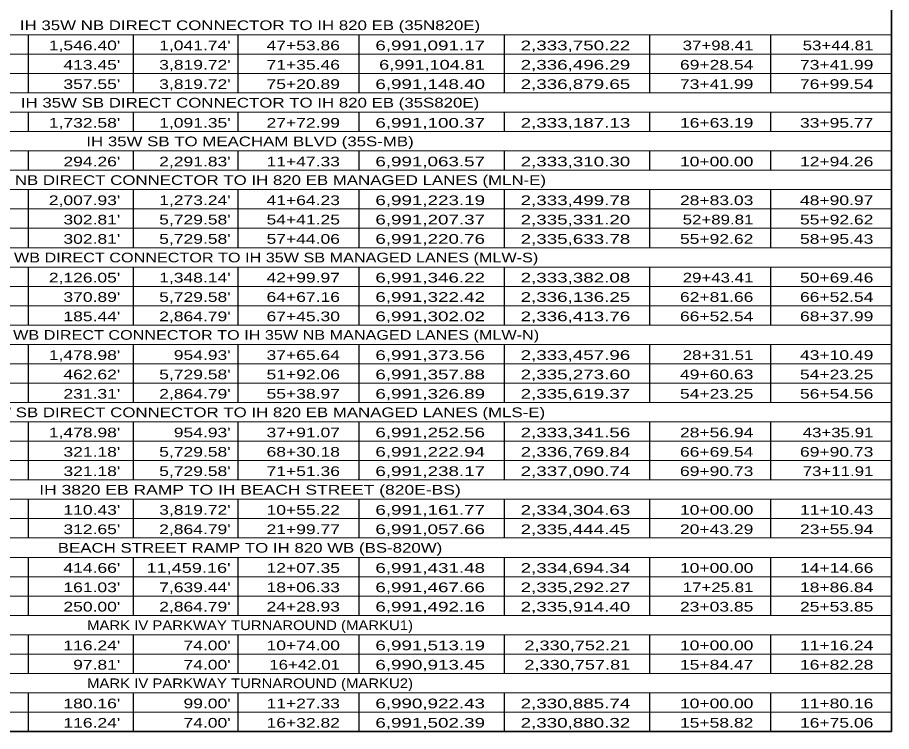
# Model space of a CAD drawing. Extents: x 1953053 to 1967065, y 7363860 to 7371201.
# Drawn here: x 1956574 to 1957657, y 7367608 to 7368493 of the extents above; entities that cross this region are included whole.
import ezdxf
from ezdxf.enums import TextEntityAlignment as Align

# ---------------------------------------------------------------- set-up
doc = ezdxf.new("R2010")
doc.units = 0
doc.header["$LTSCALE"] = 4.8
doc.layers.add('10', color=7, linetype='Continuous')
doc.layers.add('12', color=7, linetype='Continuous', lineweight=25)

msp = doc.modelspace()

# ---------------------------------------------------------------- linework, layer by layer
at = {"layer": '12', "lineweight": 35}
for p, q in [((1957656.717, 7367607.746), (1957656.717, 7370164.879)), ((1955933.385, 7367607.746), (1957656.717, 7367607.746))]:
    msp.add_line(p, q, dxfattribs=at)
at = {"layer": '12', "lineweight": 13}
for p, q in [((1955933.385, 7368471.746), (1957656.717, 7368471.746)), ((1955933.385, 7368447.746), (1957656.717, 7368447.746)), ((1955933.385, 7368423.746), (1957656.717, 7368423.746)), ((1955933.385, 7368399.746), (1957656.717, 7368399.746)), ((1955933.385, 7368375.746), (1957656.717, 7368375.746)), ((1955933.385, 7368351.746), (1957656.717, 7368351.746)), ((1955933.385, 7368327.746), (1957656.717, 7368327.746)), ((1955933.385, 7368303.746), (1957656.717, 7368303.746)), ((1955933.385, 7368279.746), (1957656.717, 7368279.746)), ((1955933.385, 7368255.746), (1957656.717, 7368255.746)), ((1955933.385, 7368231.746), (1957656.717, 7368231.746)), ((1955933.385, 7368207.746), (1957656.717, 7368207.746)), ((1955933.385, 7368183.746), (1957656.717, 7368183.746)), ((1955933.385, 7368159.746), (1957656.717, 7368159.746)), ((1955933.385, 7368135.746), (1957656.717, 7368135.746)), ((1955933.385, 7368111.746), (1957656.717, 7368111.746)), ((1955933.385, 7368087.746), (1957656.717, 7368087.746)), ((1955933.385, 7368063.746), (1957656.717, 7368063.746)), ((1955933.385, 7368039.746), (1957656.717, 7368039.746)), ((1955933.385, 7368015.746), (1957656.717, 7368015.746)), ((1955933.385, 7367991.746), (1957656.717, 7367991.746)), ((1955933.385, 7367967.746), (1957656.717, 7367967.746)), ((1955933.385, 7367943.746), (1957656.717, 7367943.746)), ((1955933.385, 7367919.746), (1957656.717, 7367919.746)), ((1955933.385, 7367895.746), (1957656.717, 7367895.746)), ((1955933.385, 7367871.746), (1957656.717, 7367871.746)), ((1955933.385, 7367847.746), (1957656.717, 7367847.746)), ((1955933.385, 7367823.746), (1957656.717, 7367823.746)), ((1955933.385, 7367799.746), (1957656.717, 7367799.746)), ((1955933.385, 7367775.746), (1957656.717, 7367775.746)), ((1955933.385, 7367751.746), (1957656.717, 7367751.746)), ((1955933.385, 7367727.746), (1957656.717, 7367727.746)), ((1955933.385, 7367703.746), (1957656.717, 7367703.746)), ((1955933.385, 7367679.746), (1957656.717, 7367679.746)), ((1955933.385, 7367655.746), (1957656.717, 7367655.746)), ((1955933.385, 7367631.746), (1957656.717, 7367631.746))]:
    msp.add_line(p, q, dxfattribs=at)
at = {"layer": '12'}
for p, q in [((1956586.717, 7368471.746), (1956586.717, 7368399.746)), ((1956716.717, 7368471.746), (1956716.717, 7368399.746)), ((1956846.717, 7368471.746), (1956846.717, 7368399.746)), ((1956996.717, 7368471.746), (1956996.717, 7368399.746)), ((1957176.717, 7368471.746), (1957176.717, 7368399.746)), ((1957356.717, 7368471.746), (1957356.717, 7368399.746)), ((1957506.717, 7368471.746), (1957506.717, 7368399.746)), ((1956586.717, 7368375.746), (1956586.717, 7368351.746)), ((1956716.717, 7368375.746), (1956716.717, 7368351.746)), ((1956846.717, 7368375.746), (1956846.717, 7368351.746)), ((1956996.717, 7368375.746), (1956996.717, 7368351.746)), ((1957176.717, 7368375.746), (1957176.717, 7368351.746)), ((1957356.717, 7368375.746), (1957356.717, 7368351.746)), ((1957506.717, 7368375.746), (1957506.717, 7368351.746)), ((1956586.717, 7368327.746), (1956586.717, 7368303.746)), ((1956716.717, 7368327.746), (1956716.717, 7368303.746)), ((1956846.717, 7368327.746), (1956846.717, 7368303.746)), ((1956996.717, 7368327.746), (1956996.717, 7368303.746)), ((1957176.717, 7368327.746), (1957176.717, 7368303.746)), ((1957356.717, 7368327.746), (1957356.717, 7368303.746)), ((1957506.717, 7368327.746), (1957506.717, 7368303.746)), ((1956586.717, 7368279.746), (1956586.717, 7368207.746)), ((1956716.717, 7368279.746), (1956716.717, 7368207.746)), ((1956846.717, 7368279.746), (1956846.717, 7368207.746)), ((1956996.717, 7368279.746), (1956996.717, 7368207.746)), ((1957176.717, 7368279.746), (1957176.717, 7368207.746)), ((1957356.717, 7368279.746), (1957356.717, 7368207.746)), ((1957506.717, 7368279.746), (1957506.717, 7368207.746)), ((1956586.717, 7368183.746), (1956586.717, 7368111.746)), ((1956716.717, 7368183.746), (1956716.717, 7368111.746)), ((1956846.717, 7368183.746), (1956846.717, 7368111.746)), ((1956996.717, 7368183.746), (1956996.717, 7368111.746)), ((1957176.717, 7368183.746), (1957176.717, 7368111.746)), ((1957356.717, 7368183.746), (1957356.717, 7368111.746)), ((1957506.717, 7368183.746), (1957506.717, 7368111.746)), ((1956586.717, 7368087.746), (1956586.717, 7368015.746)), ((1956716.717, 7368087.746), (1956716.717, 7368015.746)), ((1956846.717, 7368087.746), (1956846.717, 7368015.746)), ((1956996.717, 7368087.746), (1956996.717, 7368015.746)), ((1957176.717, 7368087.746), (1957176.717, 7368015.746)), ((1957356.717, 7368087.746), (1957356.717, 7368015.746)), ((1957506.717, 7368087.746), (1957506.717, 7368015.746)), ((1956586.717, 7367991.746), (1956586.717, 7367919.746)), ((1956716.717, 7367991.746), (1956716.717, 7367919.746)), ((1956846.717, 7367991.746), (1956846.717, 7367919.746)), ((1956996.717, 7367991.746), (1956996.717, 7367919.746)), ((1957176.717, 7367991.746), (1957176.717, 7367919.746)), ((1957356.717, 7367991.746), (1957356.717, 7367919.746)), ((1957506.717, 7367991.746), (1957506.717, 7367919.746)), ((1956586.717, 7367895.746), (1956586.717, 7367847.746)), ((1956716.717, 7367895.746), (1956716.717, 7367847.746)), ((1956846.717, 7367895.746), (1956846.717, 7367847.746)), ((1956996.717, 7367895.746), (1956996.717, 7367847.746)), ((1957176.717, 7367895.746), (1957176.717, 7367847.746)), ((1957356.717, 7367895.746), (1957356.717, 7367847.746)), ((1957506.717, 7367895.746), (1957506.717, 7367847.746)), ((1956586.717, 7367823.746), (1956586.717, 7367751.746)), ((1956716.717, 7367823.746), (1956716.717, 7367751.746)), ((1956846.717, 7367823.746), (1956846.717, 7367751.746)), ((1956996.717, 7367823.746), (1956996.717, 7367751.746)), ((1957176.717, 7367823.746), (1957176.717, 7367751.746)), ((1957356.717, 7367823.746), (1957356.717, 7367751.746)), ((1957506.717, 7367823.746), (1957506.717, 7367751.746)), ((1956586.717, 7367727.746), (1956586.717, 7367679.746)), ((1956716.717, 7367727.746), (1956716.717, 7367679.746)), ((1956846.717, 7367727.746), (1956846.717, 7367679.746)), ((1956996.717, 7367727.746), (1956996.717, 7367679.746)), ((1957176.717, 7367727.746), (1957176.717, 7367679.746)), ((1957356.717, 7367727.746), (1957356.717, 7367679.746)), ((1957506.717, 7367727.746), (1957506.717, 7367679.746)), ((1956586.717, 7367655.746), (1956586.717, 7367607.746)), ((1956716.717, 7367655.746), (1956716.717, 7367607.746)), ((1956846.717, 7367655.746), (1956846.717, 7367607.746)), ((1956996.717, 7367655.746), (1956996.717, 7367607.746)), ((1957176.717, 7367655.746), (1957176.717, 7367607.746)), ((1957356.717, 7367655.746), (1957356.717, 7367607.746)), ((1957506.717, 7367655.746), (1957506.717, 7367607.746))]:
    msp.add_line(p, q, dxfattribs=at)

# ---------------------------------------------------------------- texts
at = {"layer": '10'}
for s, width, p in [('IH 35W NB DIRECT CONNECTOR TO IH 820 EB (35N820E)', 1.3, (1956861.717, 7368477.54)), ('IH 35W SB DIRECT CONNECTOR TO IH 820 EB (35S820E)', 1.3, (1956861.717, 7368381.54)), ('IH 35W SB TO MEACHAM BLVD (35S-MB)', 1.3, (1956861.718, 7368333.54)), ('IH 35W NB DIRECT CONNECTOR TO IH 820 EB MANAGED LANES (MLN-E)', 1.3, (1956861.718, 7368285.54)), ('IH 820 WB DIRECT CONNECTOR TO IH 35W SB MANAGED LANES (MLW-S)', 1.25, (1956861.718, 7368189.54)), ('IH 820 WB DIRECT CONNECTOR TO IH 35W NB MANAGED LANES (MLW-N)', 1.25, (1956861.718, 7368093.54)), ('IH 35W SB DIRECT CONNECTOR TO IH 820 EB MANAGED LANES (MLS-E)', 1.3, (1956861.718, 7367997.54)), ('IH 3820 EB RAMP TO IH BEACH STREET (820E-BS)', 1.35, (1956861.718, 7367901.54)), ('BEACH STREET RAMP TO IH 820 WB (BS-820W)', 1.3, (1956861.717, 7367829.54)), ('MARK IV PARKWAY TURNAROUND (MARKU1)', 1.15, (1956861.717, 7367733.54)), ('MARK IV PARKWAY TURNAROUND (MARKU2)', 1.15, (1956861.717, 7367661.54))]:
    msp.add_text(s, height=12, dxfattribs=dict(at, width=width)).set_placement(p, align=Align.CENTER)
for s, width, p in [("1,546.40'", 1.35, (1956700.846, 7368452.569)), ("1,041.74'", 1.35, (1956837.615, 7368452.569)), ('47+53.86', 1.35, (1956973.159, 7368452.569)), ('6,991,091.17', 1.45, (1957152.924, 7368452.569)), ('2,333,750.22', 1.45, (1957332.924, 7368452.569)), ('37+98.41', 1.3, (1957485.502, 7368452.569)), ('53+44.81', 1.3, (1957634.234, 7368452.569)), ("413.45'", 1.35, (1956700.846, 7368428.569)), ("3,819.72'", 1.35, (1956837.615, 7368428.569)), ('71+35.46', 1.35, (1956973.159, 7368428.569)), ('6,991,104.81', 1.4, (1957152.924, 7368428.569)), ('2,336,496.29', 1.45, (1957332.924, 7368428.569)), ('69+28.54', 1.35, (1957485.502, 7368428.569)), ('73+41.99', 1.35, (1957634.234, 7368428.569)), ("357.55'", 1.35, (1956700.846, 7368404.569)), ("3,819.72'", 1.35, (1956837.615, 7368404.569)), ('75+20.89', 1.35, (1956973.159, 7368404.569)), ('6,991,148.40', 1.45, (1957152.924, 7368404.569)), ('2,336,879.65', 1.45, (1957332.924, 7368404.569)), ('73+41.99', 1.35, (1957485.502, 7368404.569)), ('76+99.54', 1.35, (1957634.234, 7368404.569)), ("1,732.58'", 1.35, (1956700.846, 7368356.569)), ("1,091.35'", 1.35, (1956837.615, 7368356.569)), ('27+72.99', 1.35, (1956973.159, 7368356.569)), ('6,991,100.37', 1.45, (1957152.924, 7368356.569)), ('2,333,187.13', 1.45, (1957332.924, 7368356.569)), ('16+63.19', 1.35, (1957485.502, 7368356.569)), ('33+95.77', 1.35, (1957634.234, 7368356.569)), ("294.26'", 1.35, (1956700.846, 7368308.569)), ("2,291.83'", 1.35, (1956837.615, 7368308.569)), ('11+47.33', 1.35, (1956973.159, 7368308.569)), ('6,991,063.57', 1.45, (1957152.924, 7368308.569)), ('2,333,310.30', 1.45, (1957332.924, 7368308.569)), ('10+00.00', 1.35, (1957485.502, 7368308.569)), ('12+94.26', 1.35, (1957634.234, 7368308.569)), ("2,007.93'", 1.35, (1956700.846, 7368260.569)), ("1,273.24'", 1.35, (1956837.615, 7368260.569)), ('41+64.23', 1.35, (1956973.159, 7368260.569)), ('6,991,223.19', 1.45, (1957152.924, 7368260.569)), ('2,333,499.78', 1.45, (1957332.924, 7368260.569)), ('28+83.03', 1.35, (1957485.502, 7368260.569)), ('48+90.97', 1.35, (1957634.234, 7368260.569)), ("302.81'", 1.35, (1956700.846, 7368236.569)), ("5,729.58'", 1.35, (1956837.615, 7368236.569)), ('54+41.25', 1.35, (1956973.159, 7368236.569)), ('6,991,207.37', 1.45, (1957152.924, 7368236.569)), ('2,335,331.20', 1.45, (1957332.924, 7368236.569)), ('52+89.81', 1.3, (1957485.502, 7368236.569)), ('55+92.62', 1.35, (1957634.234, 7368236.569)), ("302.81'", 1.35, (1956700.846, 7368212.569)), ("5,729.58'", 1.35, (1956837.615, 7368212.569)), ('57+44.06', 1.35, (1956973.159, 7368212.569)), ('6,991,220.76', 1.45, (1957152.924, 7368212.569)), ('2,335,633.78', 1.45, (1957332.924, 7368212.569)), ('55+92.62', 1.35, (1957485.502, 7368212.569)), ('58+95.43', 1.35, (1957634.234, 7368212.569)), ("2,126.05'", 1.35, (1956700.846, 7368164.569)), ("1,348.14'", 1.35, (1956837.615, 7368164.569)), ('42+99.97', 1.35, (1956973.159, 7368164.569)), ('6,991,346.22', 1.45, (1957152.924, 7368164.569)), ('2,333,382.08', 1.45, (1957332.924, 7368164.569)), ('29+43.41', 1.3, (1957485.502, 7368164.569)), ('50+69.46', 1.35, (1957634.234, 7368164.569)), ("370.89'", 1.35, (1956700.846, 7368140.569)), ("5,729.58'", 1.35, (1956837.615, 7368140.569)), ('64+67.16', 1.35, (1956973.159, 7368140.569)), ('6,991,322.42', 1.45, (1957152.924, 7368140.569)), ('2,336,136.25', 1.45, (1957332.924, 7368140.569)), ('62+81.66', 1.35, (1957485.502, 7368140.569)), ('66+52.54', 1.35, (1957634.234, 7368140.569)), ("185.44'", 1.35, (1956700.846, 7368116.569)), ("2,864.79'", 1.35, (1956837.615, 7368116.569)), ('67+45.30', 1.35, (1956973.159, 7368116.569)), ('6,991,302.02', 1.45, (1957152.924, 7368116.569)), ('2,336,413.76', 1.45, (1957332.924, 7368116.569)), ('66+52.54', 1.35, (1957485.502, 7368116.569)), ('68+37.99', 1.35, (1957634.234, 7368116.569)), ("1,478.98'", 1.35, (1956700.846, 7368068.569)), ("954.93'", 1.35, (1956837.615, 7368068.569)), ('37+65.64', 1.35, (1956973.159, 7368068.569)), ('6,991,373.56', 1.45, (1957152.924, 7368068.569)), ('2,333,457.96', 1.45, (1957332.924, 7368068.569)), ('28+31.51', 1.3, (1957485.502, 7368068.569)), ('43+10.49', 1.35, (1957634.234, 7368068.569)), ("462.62'", 1.35, (1956700.846, 7368044.569)), ("5,729.58'", 1.35, (1956837.615, 7368044.569)), ('51+92.06', 1.35, (1956973.159, 7368044.569)), ('6,991,357.88', 1.45, (1957152.924, 7368044.569)), ('2,335,273.60', 1.45, (1957332.924, 7368044.569)), ('49+60.63', 1.35, (1957485.502, 7368044.569)), ('54+23.25', 1.35, (1957634.234, 7368044.569)), ("231.31'", 1.35, (1956700.846, 7368020.569)), ("2,864.79'", 1.35, (1956837.615, 7368020.569)), ('55+38.97', 1.35, (1956973.159, 7368020.569)), ('6,991,326.89', 1.45, (1957152.924, 7368020.569)), ('2,335,619.37', 1.45, (1957332.924, 7368020.569)), ('54+23.25', 1.35, (1957485.502, 7368020.569)), ('56+54.56', 1.35, (1957634.234, 7368020.569)), ("1,478.98'", 1.35, (1956700.846, 7367972.569)), ("954.93'", 1.35, (1956837.615, 7367972.569)), ('37+91.07', 1.35, (1956973.159, 7367972.569)), ('6,991,252.56', 1.45, (1957152.924, 7367972.569)), ('2,333,341.56', 1.45, (1957332.924, 7367972.569)), ('28+56.94', 1.35, (1957485.502, 7367972.569)), ('43+35.91', 1.3, (1957634.234, 7367972.569)), ("321.18'", 1.35, (1956700.846, 7367948.569)), ("5,729.58'", 1.35, (1956837.615, 7367948.569)), ('68+30.18', 1.35, (1956973.159, 7367948.569)), ('6,991,222.94', 1.45, (1957152.924, 7367948.569)), ('2,336,769.84', 1.45, (1957332.924, 7367948.569)), ('66+69.54', 1.35, (1957485.502, 7367948.569)), ('69+90.73', 1.35, (1957634.234, 7367948.569)), ("321.18'", 1.35, (1956700.846, 7367924.569)), ("5,729.58'", 1.35, (1956837.615, 7367924.569)), ('71+51.36', 1.35, (1956973.159, 7367924.569)), ('6,991,238.17', 1.45, (1957152.924, 7367924.569)), ('2,337,090.74', 1.45, (1957332.924, 7367924.569)), ('69+90.73', 1.35, (1957485.502, 7367924.569)), ('73+11.91', 1.3, (1957634.234, 7367924.569)), ("110.43'", 1.35, (1956700.846, 7367876.569)), ("3,819.72'", 1.35, (1956837.615, 7367876.569)), ('10+55.22', 1.35, (1956973.159, 7367876.569)), ('6,991,161.77', 1.45, (1957152.924, 7367876.569)), ('2,334,304.63', 1.45, (1957332.924, 7367876.569)), ('10+00.00', 1.35, (1957485.502, 7367876.569)), ('11+10.43', 1.35, (1957634.234, 7367876.569)), ("312.65'", 1.35, (1956700.846, 7367852.569)), ("2,864.79'", 1.35, (1956837.615, 7367852.569)), ('21+99.77', 1.35, (1956973.159, 7367852.569)), ('6,991,057.66', 1.45, (1957152.924, 7367852.569)), ('2,335,444.45', 1.45, (1957332.924, 7367852.569)), ('20+43.29', 1.35, (1957485.502, 7367852.569)), ('23+55.94', 1.35, (1957634.234, 7367852.569)), ("414.66'", 1.35, (1956700.846, 7367804.569)), ("11,459.16'", 1.4, (1956837.615, 7367804.569)), ('12+07.35', 1.35, (1956973.159, 7367804.569)), ('6,991,431.48', 1.45, (1957152.924, 7367804.569)), ('2,334,694.34', 1.45, (1957332.924, 7367804.569)), ('10+00.00', 1.35, (1957485.502, 7367804.569)), ('14+14.66', 1.35, (1957634.234, 7367804.569)), ("161.03'", 1.35, (1956700.846, 7367780.569)), ("7,639.44'", 1.35, (1956837.615, 7367780.569)), ('18+06.33', 1.35, (1956973.159, 7367780.569)), ('6,991,467.66', 1.45, (1957152.924, 7367780.569)), ('2,335,292.27', 1.45, (1957332.924, 7367780.569)), ('17+25.81', 1.3, (1957485.502, 7367780.569)), ('18+86.84', 1.35, (1957634.234, 7367780.569)), ("250.00'", 1.35, (1956700.846, 7367756.569)), ("2,864.79'", 1.35, (1956837.615, 7367756.569)), ('24+28.93', 1.35, (1956973.159, 7367756.569)), ('6,991,492.16', 1.45, (1957152.924, 7367756.569)), ('2,335,914.40', 1.45, (1957332.924, 7367756.569)), ('23+03.85', 1.35, (1957485.502, 7367756.569)), ('25+53.85', 1.35, (1957634.234, 7367756.569)), ("116.24'", 1.35, (1956700.841, 7367708.573)), ("74.00'", 1.35, (1956837.61, 7367708.573)), ('10+74.00', 1.35, (1956973.154, 7367708.573)), ('6,991,513.19', 1.45, (1957152.919, 7367708.573)), ('2,330,752.21', 1.4, (1957332.919, 7367708.573)), ('10+00.00', 1.35, (1957485.497, 7367708.573)), ('11+16.24', 1.35, (1957634.229, 7367708.573)), ("97.81'", 1.35, (1956700.841, 7367684.573)), ("74.00'", 1.35, (1956837.61, 7367684.573)), ('16+42.01', 1.3, (1956973.154, 7367684.573)), ('6,990,913.45', 1.45, (1957152.919, 7367684.573)), ('2,330,757.81', 1.4, (1957332.919, 7367684.573)), ('15+84.47', 1.35, (1957485.497, 7367684.573)), ('16+82.28', 1.35, (1957634.229, 7367684.573)), ("180.16'", 1.35, (1956700.841, 7367636.573)), ("99.00'", 1.35, (1956837.61, 7367636.573)), ('11+27.33', 1.35, (1956973.154, 7367636.573)), ('6,990,922.43', 1.45, (1957152.919, 7367636.573)), ('2,330,885.74', 1.45, (1957332.919, 7367636.573)), ('10+00.00', 1.35, (1957485.497, 7367636.573)), ('11+80.16', 1.35, (1957634.229, 7367636.573)), ("116.24'", 1.35, (1956700.841, 7367612.573)), ("74.00'", 1.35, (1956837.61, 7367612.573)), ('16+32.82', 1.35, (1956973.154, 7367612.573)), ('6,991,502.39', 1.45, (1957152.919, 7367612.573)), ('2,330,880.32', 1.45, (1957332.919, 7367612.573)), ('15+58.82', 1.35, (1957485.497, 7367612.573)), ('16+75.06', 1.35, (1957634.229, 7367612.573))]:
    msp.add_text(s, height=12, dxfattribs=dict(at, width=width)).set_placement(p, align=Align.RIGHT)

doc.saveas('drawing.dxf')
